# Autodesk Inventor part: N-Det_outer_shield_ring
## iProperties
Shininess: 64.0
Length Units: 11269
Angle Units: 11279
Time Units: 11290
Mass Units: 11283
Length Display Precision: 3
Angle Display Precision: 2
Compacted: True
Part Number: N-Det_outer_shield_ring
Document SubType Name: Modeling
Created: 2005-04
Designer: John Blackburn
Manufacturer: Standard
Standards Organization: Custom
Material: Stainless Steel, Austenitic
Density: 0.0
Volumn: 0.0
Area: 0.0
PropertySet Name: Model Information
Control State: 0
Master: False
Checked Out: False
Author: John Blackburn
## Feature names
1. Extrusion1
2. Chamfer1
